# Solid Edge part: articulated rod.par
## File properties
Author: Robert a Rhodes jr
Template: Normal.par
Last saved by: CADCIM
Revision: 20
Application: Solid Edge
Accuracy: 0.99
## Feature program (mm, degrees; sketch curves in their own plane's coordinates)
pattern "unnamed Pattern 1"
pattern "unnamed Pattern 2"
Other named dimensions: "Hole_2": Diameter = 15 mm
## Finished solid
Body 1: solid body, 26 faces, 56 edges, 32 vertices.
  Faces by surface: plane 14, cylinder 12
  Edges by curve: circle 28, line 28
Bounding box of the edges (mm): 207.500 x 35.000 x 42.000, from (-101, -17.5, -21) to (106.5, 17.5, 21).
Cylindrical faces by radius (mm): R6.35 x4, R7.5 x1, R12 x2, R17.5 x1, R24 x4
Planar faces by outward normal: +y 3, +z 4, -y 3, -z 4
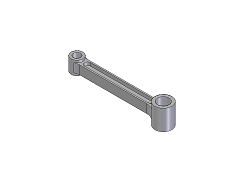
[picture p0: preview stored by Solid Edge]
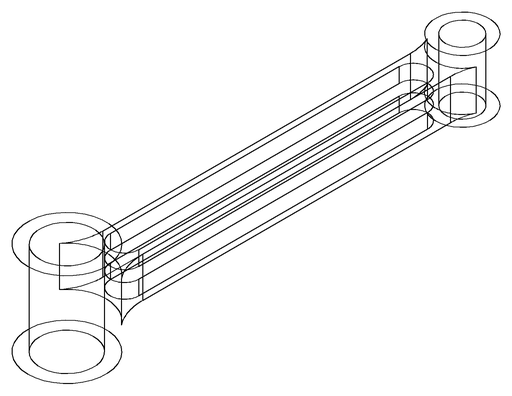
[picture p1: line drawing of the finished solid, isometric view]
